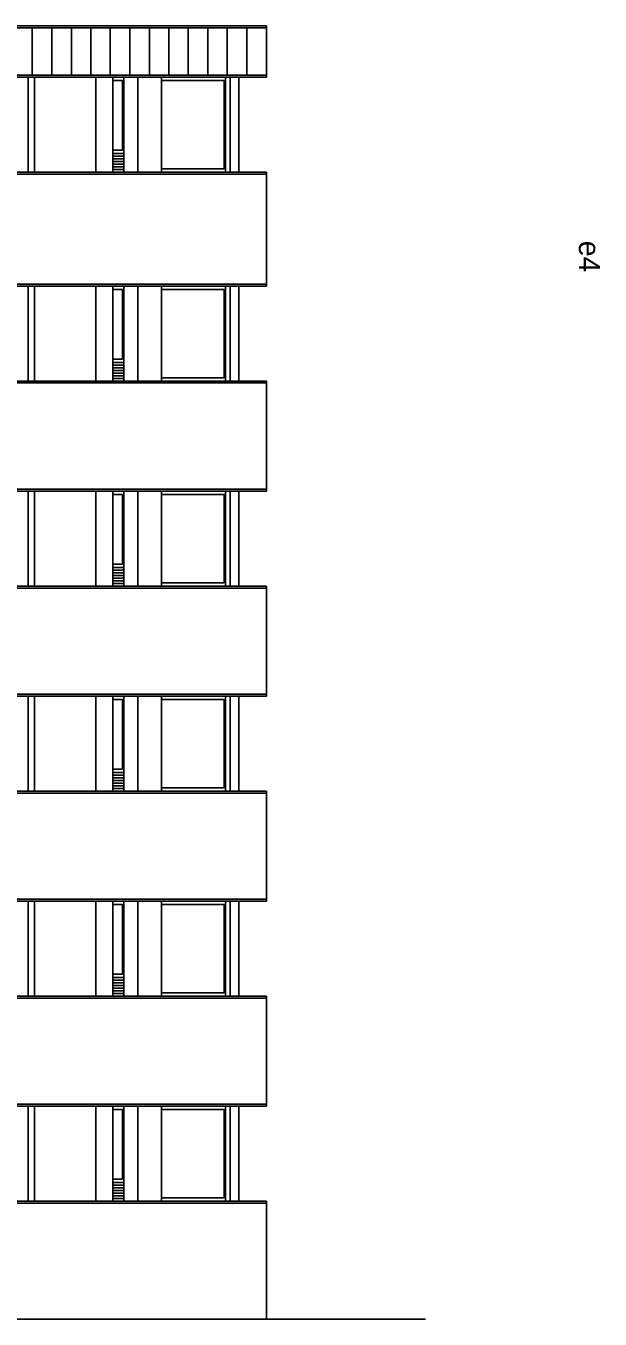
# Model space of a CAD drawing. Extents: x -4333 to -3435, y 16386 to 16556.
# Drawn here: x -3477.71 to -3469.03, y 16466.25 to 16485.81 of the extents above; entities that cross this region are included whole.
import ezdxf

# ---------------------------------------------------------------- set-up
doc = ezdxf.new("R2010")
doc.units = 0
for name, color, linetype in [('Level 2', 7, 'Continuous'), ('Level 25', 7, 'Continuous'), ('Level 40', 7, 'Continuous'), ('Level 5', 7, 'Continuous'), ('Level 63', 7, 'Continuous')]:
    doc.layers.add(name, color=color, linetype=linetype)

msp = doc.modelspace()

# ---------------------------------------------------------------- linework, layer by layer
at = {"layer": 'Level 2'}
msp.add_line((-3471.667, 16466.254), (-3567.213, 16466.253), dxfattribs=at)
at = {"layer": 'Level 25'}
for p, q in [((-3477.612, 16485.778), (-3477.612, 16485.063)), ((-3477.317, 16485.778), (-3477.317, 16485.063)), ((-3477.022, 16485.778), (-3477.022, 16485.063)), ((-3476.728, 16485.778), (-3476.728, 16485.063)), ((-3476.433, 16485.778), (-3476.433, 16485.063)), ((-3476.138, 16485.778), (-3476.138, 16485.063)), ((-3475.843, 16485.778), (-3475.843, 16485.063)), ((-3475.548, 16485.778), (-3475.548, 16485.063)), ((-3475.254, 16485.778), (-3475.254, 16485.063)), ((-3474.959, 16485.778), (-3474.959, 16485.063)), ((-3474.664, 16485.778), (-3474.664, 16485.063)), ((-3474.369, 16485.778), (-3474.369, 16485.063))]:
    msp.add_line(p, q, dxfattribs=at)
at = {"layer": 'Level 40'}
for points in [[(-3491.627, 16485.808), (-3474.074, 16485.808), (-3474.074, 16485.033), (-3491.627, 16485.033)], [(-3478.614, 16485.033), (-3477.58, 16485.033), (-3477.58, 16483.598), (-3478.614, 16483.598)], [(-3477.58, 16485.033), (-3476.396, 16485.033), (-3476.396, 16483.598), (-3477.58, 16483.598)], [(-3476.23, 16485.033), (-3475.659, 16485.033), (-3475.659, 16483.598), (-3476.23, 16483.598)], [(-3474.693, 16485.033), (-3474.491, 16485.033), (-3474.491, 16483.598), (-3474.693, 16483.598)], [(-3478.614, 16481.873), (-3477.58, 16481.873), (-3477.58, 16480.438), (-3478.614, 16480.438)], [(-3477.58, 16481.873), (-3476.396, 16481.873), (-3476.396, 16480.438), (-3477.58, 16480.438)], [(-3476.229, 16481.873), (-3475.659, 16481.873), (-3475.659, 16480.438), (-3476.229, 16480.438)], [(-3474.693, 16481.873), (-3474.491, 16481.873), (-3474.491, 16480.438), (-3474.693, 16480.438)], [(-3478.614, 16478.773), (-3477.58, 16478.773), (-3477.58, 16477.338), (-3478.614, 16477.338)], [(-3477.58, 16478.773), (-3476.396, 16478.773), (-3476.396, 16477.338), (-3477.58, 16477.338)], [(-3476.229, 16478.773), (-3475.659, 16478.773), (-3475.659, 16477.338), (-3476.229, 16477.338)], [(-3474.693, 16478.773), (-3474.491, 16478.773), (-3474.491, 16477.338), (-3474.693, 16477.338)], [(-3478.614, 16475.673), (-3477.58, 16475.673), (-3477.58, 16474.238), (-3478.614, 16474.238)], [(-3477.58, 16475.673), (-3476.396, 16475.673), (-3476.396, 16474.238), (-3477.58, 16474.238)], [(-3476.229, 16475.673), (-3475.659, 16475.673), (-3475.659, 16474.238), (-3476.229, 16474.238)], [(-3474.693, 16475.673), (-3474.491, 16475.673), (-3474.491, 16474.238), (-3474.693, 16474.238)], [(-3478.614, 16472.573), (-3477.58, 16472.573), (-3477.58, 16471.138), (-3478.614, 16471.138)], [(-3477.58, 16472.573), (-3476.396, 16472.573), (-3476.396, 16471.138), (-3477.58, 16471.138)], [(-3476.229, 16472.573), (-3475.659, 16472.573), (-3475.659, 16471.138), (-3476.229, 16471.138)], [(-3474.693, 16472.573), (-3474.491, 16472.573), (-3474.491, 16471.138), (-3474.693, 16471.138)], [(-3478.614, 16469.473), (-3477.58, 16469.473), (-3477.58, 16468.038), (-3478.614, 16468.038)], [(-3477.58, 16469.473), (-3476.396, 16469.473), (-3476.396, 16468.038), (-3477.58, 16468.038)], [(-3476.229, 16469.473), (-3475.659, 16469.473), (-3475.659, 16468.038), (-3476.229, 16468.038)], [(-3474.693, 16469.473), (-3474.491, 16469.473), (-3474.491, 16468.038), (-3474.693, 16468.038)]]:
    msp.add_lwpolyline(points, close=True, dxfattribs=at)
at = {"layer": 'Level 63'}
for p, q in [((-3474.074, 16485.808), (-3491.627, 16485.808)), ((-3474.074, 16485.778), (-3491.627, 16485.778)), ((-3474.074, 16485.808), (-3474.074, 16485.033)), ((-3491.625, 16485.063), (-3474.074, 16485.063)), ((-3491.625, 16485.033), (-3474.074, 16485.033)), ((-3477.677, 16485.033), (-3477.677, 16483.598)), ((-3477.58, 16485.033), (-3477.58, 16483.598)), ((-3476.651, 16485.033), (-3476.651, 16483.598)), ((-3476.396, 16485.033), (-3476.396, 16483.598)), ((-3476.396, 16484.983), (-3476.249, 16484.983)), ((-3476.249, 16484.983), (-3476.249, 16483.928)), ((-3476.23, 16485.033), (-3476.23, 16483.598)), ((-3476.017, 16485.033), (-3476.017, 16483.598)), ((-3475.659, 16485.033), (-3475.659, 16483.598)), ((-3475.659, 16484.983), (-3474.713, 16484.983)), ((-3474.713, 16484.983), (-3474.713, 16483.648)), ((-3474.693, 16485.033), (-3474.693, 16483.598)), ((-3474.62, 16485.033), (-3474.62, 16483.598)), ((-3474.491, 16485.033), (-3474.491, 16483.598)), ((-3476.249, 16483.928), (-3476.396, 16483.928)), ((-3476.231, 16483.878), (-3476.396, 16483.878)), ((-3476.231, 16483.838), (-3476.396, 16483.838)), ((-3476.231, 16483.798), (-3476.396, 16483.798)), ((-3491.625, 16483.598), (-3474.074, 16483.598)), ((-3476.231, 16483.758), (-3476.396, 16483.758)), ((-3476.231, 16483.718), (-3476.396, 16483.718)), ((-3476.231, 16483.678), (-3476.396, 16483.678)), ((-3476.231, 16483.638), (-3476.396, 16483.638)), ((-3475.659, 16483.648), (-3474.713, 16483.648)), ((-3474.074, 16483.598), (-3474.074, 16481.873)), ((-3491.625, 16483.568), (-3474.074, 16483.568)), ((-3491.625, 16481.903), (-3474.074, 16481.903)), ((-3491.625, 16481.873), (-3474.074, 16481.873)), ((-3477.677, 16481.873), (-3477.677, 16480.438)), ((-3477.58, 16481.873), (-3477.58, 16480.438)), ((-3476.651, 16481.873), (-3476.651, 16480.438)), ((-3476.396, 16481.873), (-3476.396, 16480.438)), ((-3476.396, 16481.823), (-3476.249, 16481.823)), ((-3476.249, 16481.823), (-3476.249, 16480.768)), ((-3476.229, 16481.873), (-3476.229, 16480.438)), ((-3476.017, 16481.873), (-3476.017, 16480.438)), ((-3475.659, 16481.873), (-3475.659, 16480.438)), ((-3475.659, 16481.823), (-3474.713, 16481.823)), ((-3474.713, 16481.823), (-3474.713, 16480.488)), ((-3474.693, 16481.873), (-3474.693, 16480.438)), ((-3474.62, 16481.873), (-3474.619, 16480.438)), ((-3474.491, 16481.873), (-3474.491, 16480.438)), ((-3476.249, 16480.768), (-3476.396, 16480.768)), ((-3476.231, 16480.718), (-3476.396, 16480.718)), ((-3476.231, 16480.678), (-3476.396, 16480.678)), ((-3476.231, 16480.638), (-3476.396, 16480.638)), ((-3476.231, 16480.598), (-3476.396, 16480.598)), ((-3476.231, 16480.558), (-3476.396, 16480.558)), ((-3476.231, 16480.518), (-3476.396, 16480.518)), ((-3476.231, 16480.478), (-3476.396, 16480.478)), ((-3475.659, 16480.488), (-3474.713, 16480.488)), ((-3491.625, 16480.438), (-3474.074, 16480.438)), ((-3491.625, 16480.408), (-3474.074, 16480.408)), ((-3474.074, 16480.438), (-3474.074, 16478.773)), ((-3491.625, 16478.803), (-3474.074, 16478.803)), ((-3491.625, 16478.773), (-3474.074, 16478.773)), ((-3477.677, 16478.773), (-3477.677, 16477.338)), ((-3477.58, 16478.773), (-3477.58, 16477.338)), ((-3476.651, 16478.773), (-3476.651, 16477.338)), ((-3476.396, 16478.773), (-3476.396, 16477.338)), ((-3476.396, 16478.723), (-3476.249, 16478.723)), ((-3476.249, 16478.723), (-3476.249, 16477.668)), ((-3476.229, 16478.773), (-3476.229, 16477.338)), ((-3476.017, 16478.773), (-3476.017, 16477.338)), ((-3475.659, 16478.773), (-3475.659, 16477.338)), ((-3475.659, 16478.723), (-3474.713, 16478.723)), ((-3474.713, 16478.723), (-3474.713, 16477.388)), ((-3474.693, 16478.773), (-3474.693, 16477.338)), ((-3474.619, 16478.773), (-3474.619, 16477.338)), ((-3474.491, 16478.773), (-3474.491, 16477.338)), ((-3476.249, 16477.668), (-3476.396, 16477.668)), ((-3476.231, 16477.618), (-3476.396, 16477.618)), ((-3476.231, 16477.578), (-3476.396, 16477.578)), ((-3476.231, 16477.538), (-3476.396, 16477.538)), ((-3491.625, 16477.338), (-3474.074, 16477.338)), ((-3476.231, 16477.498), (-3476.396, 16477.498)), ((-3476.231, 16477.458), (-3476.396, 16477.458)), ((-3476.231, 16477.418), (-3476.396, 16477.418)), ((-3476.231, 16477.378), (-3476.396, 16477.378)), ((-3475.659, 16477.388), (-3474.713, 16477.388)), ((-3474.074, 16477.338), (-3474.074, 16475.673)), ((-3491.625, 16477.308), (-3474.074, 16477.308)), ((-3491.625, 16475.703), (-3474.074, 16475.703)), ((-3491.625, 16475.673), (-3474.074, 16475.673)), ((-3477.677, 16475.673), (-3477.677, 16474.238)), ((-3477.58, 16475.673), (-3477.58, 16474.238)), ((-3476.651, 16475.673), (-3476.651, 16474.238)), ((-3476.396, 16475.673), (-3476.396, 16474.238)), ((-3476.396, 16475.623), (-3476.249, 16475.623)), ((-3476.249, 16475.623), (-3476.249, 16474.568)), ((-3476.229, 16475.673), (-3476.229, 16474.238)), ((-3476.017, 16475.673), (-3476.017, 16474.238)), ((-3475.659, 16475.673), (-3475.659, 16474.238)), ((-3475.659, 16475.623), (-3474.713, 16475.623)), ((-3474.713, 16475.623), (-3474.713, 16474.288)), ((-3474.693, 16475.673), (-3474.693, 16474.238)), ((-3474.619, 16475.673), (-3474.619, 16474.238)), ((-3474.491, 16475.673), (-3474.491, 16474.238)), ((-3476.249, 16474.568), (-3476.396, 16474.568)), ((-3476.231, 16474.518), (-3476.396, 16474.518)), ((-3476.231, 16474.478), (-3476.396, 16474.478)), ((-3476.231, 16474.438), (-3476.396, 16474.438)), ((-3476.231, 16474.398), (-3476.396, 16474.398)), ((-3491.625, 16474.238), (-3474.074, 16474.238)), ((-3491.625, 16474.208), (-3474.074, 16474.208)), ((-3476.231, 16474.358), (-3476.396, 16474.358)), ((-3476.231, 16474.318), (-3476.396, 16474.318)), ((-3476.231, 16474.278), (-3476.396, 16474.278)), ((-3475.659, 16474.288), (-3474.713, 16474.288)), ((-3474.074, 16474.238), (-3474.074, 16472.573)), ((-3491.625, 16472.603), (-3474.074, 16472.603)), ((-3491.625, 16472.573), (-3474.074, 16472.573)), ((-3477.677, 16472.573), (-3477.677, 16471.138)), ((-3477.58, 16472.573), (-3477.58, 16471.138)), ((-3476.651, 16472.573), (-3476.651, 16471.138)), ((-3476.396, 16472.573), (-3476.396, 16471.138)), ((-3476.396, 16472.523), (-3476.249, 16472.523)), ((-3476.249, 16472.523), (-3476.249, 16471.468)), ((-3476.229, 16472.573), (-3476.229, 16471.138)), ((-3476.017, 16472.573), (-3476.017, 16471.138)), ((-3475.659, 16472.573), (-3475.659, 16471.138)), ((-3475.659, 16472.523), (-3474.713, 16472.523)), ((-3474.713, 16472.523), (-3474.713, 16471.188)), ((-3474.693, 16472.573), (-3474.693, 16471.138)), ((-3474.619, 16472.573), (-3474.619, 16471.138)), ((-3474.491, 16472.573), (-3474.491, 16471.138)), ((-3476.249, 16471.468), (-3476.396, 16471.468)), ((-3476.231, 16471.418), (-3476.396, 16471.418)), ((-3476.231, 16471.378), (-3476.396, 16471.378)), ((-3476.231, 16471.338), (-3476.396, 16471.338)), ((-3476.231, 16471.298), (-3476.396, 16471.298)), ((-3491.625, 16471.138), (-3474.074, 16471.138)), ((-3491.625, 16471.108), (-3474.074, 16471.108)), ((-3476.231, 16471.258), (-3476.396, 16471.258)), ((-3476.231, 16471.218), (-3476.396, 16471.218)), ((-3476.231, 16471.178), (-3476.396, 16471.178)), ((-3475.659, 16471.188), (-3474.713, 16471.188)), ((-3474.074, 16471.138), (-3474.074, 16469.473)), ((-3491.625, 16469.503), (-3474.074, 16469.503)), ((-3491.625, 16469.473), (-3474.074, 16469.473)), ((-3477.677, 16469.473), (-3477.677, 16468.038)), ((-3477.58, 16469.473), (-3477.58, 16468.038)), ((-3476.651, 16469.473), (-3476.651, 16468.038)), ((-3476.396, 16469.473), (-3476.396, 16468.038)), ((-3476.396, 16469.423), (-3476.249, 16469.423)), ((-3476.249, 16469.423), (-3476.249, 16468.368)), ((-3476.229, 16469.473), (-3476.229, 16468.038)), ((-3476.017, 16469.473), (-3476.017, 16468.038)), ((-3475.659, 16469.473), (-3475.659, 16468.038)), ((-3475.659, 16469.423), (-3474.713, 16469.423)), ((-3474.713, 16469.423), (-3474.713, 16468.088)), ((-3474.693, 16469.473), (-3474.693, 16468.038)), ((-3474.619, 16469.473), (-3474.619, 16468.038)), ((-3474.491, 16469.473), (-3474.491, 16468.038)), ((-3476.249, 16468.368), (-3476.396, 16468.368)), ((-3476.231, 16468.318), (-3476.396, 16468.318)), ((-3476.231, 16468.278), (-3476.396, 16468.278)), ((-3476.231, 16468.238), (-3476.396, 16468.238)), ((-3476.231, 16468.198), (-3476.396, 16468.198)), ((-3476.231, 16468.158), (-3476.396, 16468.158)), ((-3490.068, 16468.038), (-3474.074, 16468.038)), ((-3490.068, 16468.008), (-3474.074, 16468.008)), ((-3476.231, 16468.118), (-3476.396, 16468.118)), ((-3476.231, 16468.078), (-3476.396, 16468.078)), ((-3475.659, 16468.088), (-3474.713, 16468.088)), ((-3474.074, 16468.038), (-3474.074, 16466.254))]:
    msp.add_line(p, q, dxfattribs=at)

# ---------------------------------------------------------------- texts
at = {"layer": 'Level 5'}
msp.add_text('e4', height=0.3203, rotation=269.9994, dxfattribs=at).set_placement((-3469.348, 16482.558))

doc.saveas('drawing.dxf')
